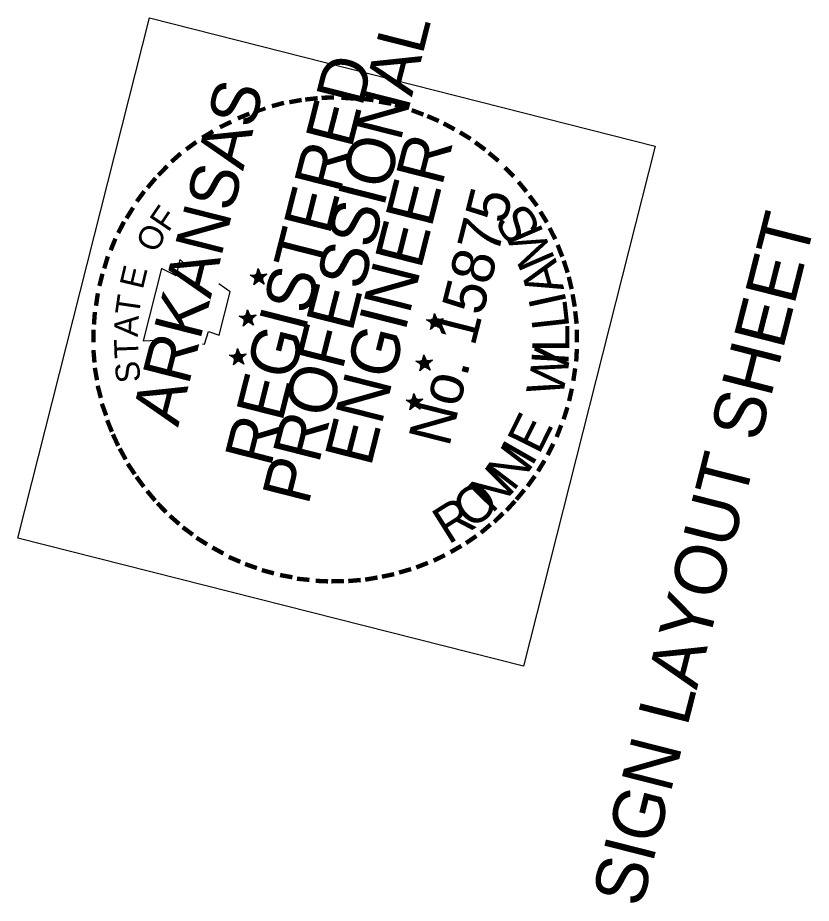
# Model space of a CAD drawing. Extents: x 670257 to 671518, y 737783 to 738188.
# Drawn here: x 670845.24 to 670853.49, y 738033.32 to 738042.53 of the extents above; entities that cross this region are included whole.
import ezdxf

# ---------------------------------------------------------------- set-up
doc = ezdxf.new("R2010")
doc.units = 0
for name, color, linetype in [('R_Border Notes', 7, 'Continuous'), ('R_Border PE', 7, 'Continuous'), ('R_Border Prem', 7, 'Continuous')]:
    doc.layers.add(name, color=color, linetype=linetype)

msp = doc.modelspace()

# ---------------------------------------------------------------- linework, layer by layer
at = {"layer": 'R_Border PE'}
for p, q in [((670847.7366, 738039.9206), (670847.7224, 738039.8443)), ((670847.7366, 738039.9206), (670847.7309, 738039.8473)), ((670847.7366, 738039.9206), (670847.7358, 738039.846)), ((670847.7366, 738039.9206), (670847.7418, 738039.829)), ((670847.7366, 738039.9206), (670847.7449, 738039.8618)), ((670847.7366, 738039.9206), (670847.748, 738039.8636)), ((670847.7366, 738039.9206), (670847.7516, 738039.8678)), ((670847.8274, 738039.8615), (670847.7418, 738039.829)), ((670847.8274, 738039.8615), (670847.7491, 738039.8478)), ((670847.8274, 738039.8615), (670847.7504, 738039.8527)), ((670847.8274, 738039.8615), (670847.7582, 738039.8429)), ((670847.8274, 738039.8615), (670847.7612, 738039.8241)), ((670847.8274, 738039.8615), (670847.766, 738039.8332)), ((670847.8274, 738039.8615), (670847.7684, 738039.8223)), ((670847.6545, 738039.8512), (670847.7194, 738039.8528)), ((670847.7418, 738039.829), (670847.6545, 738039.8512)), ((670847.6545, 738039.8512), (670847.7182, 738039.8479)), ((670847.6545, 738039.8512), (670847.7139, 738039.8413)), ((670847.6545, 738039.8512), (670847.7139, 738039.831)), ((670847.6545, 738039.8512), (670847.7127, 738039.8261)), ((670847.6545, 738039.8512), (670847.709, 738039.8219)), ((670847.6936, 738039.751), (670847.7418, 738039.829)), ((670847.6936, 738039.751), (670847.7169, 738039.8122)), ((670847.6936, 738039.751), (670847.7211, 738039.8085)), ((670847.6936, 738039.751), (670847.7235, 738039.8079)), ((670847.6936, 738039.751), (670847.7326, 738039.803)), ((670847.6936, 738039.751), (670847.7374, 738039.8018)), ((670847.6936, 738039.751), (670847.7423, 738039.8005)), ((670847.801, 738039.7573), (670847.7405, 738039.8036)), ((670847.801, 738039.7573), (670847.7418, 738039.829)), ((670847.801, 738039.7573), (670847.7484, 738039.8042)), ((670847.801, 738039.7573), (670847.752, 738039.8084)), ((670847.801, 738039.7573), (670847.7611, 738039.8138)), ((670847.801, 738039.7573), (670847.7612, 738039.8241)), ((670847.801, 738039.7573), (670847.7691, 738039.8247)), ((670847.6254, 738039.4923), (670847.6112, 738039.416)), ((670847.6254, 738039.4923), (670847.6197, 738039.419)), ((670847.6254, 738039.4923), (670847.6246, 738039.4177)), ((670847.6254, 738039.4923), (670847.6306, 738039.4007)), ((670847.6254, 738039.4923), (670847.6337, 738039.4335)), ((670847.6254, 738039.4923), (670847.6374, 738039.4377)), ((670847.6254, 738039.4923), (670847.6404, 738039.4395)), ((670847.5409, 738039.4235), (670847.6082, 738039.4245)), ((670847.6306, 738039.4007), (670847.5409, 738039.4235)), ((670847.5409, 738039.4235), (670847.6046, 738039.4202)), ((670847.5409, 738039.4235), (670847.6027, 738039.413)), ((670847.5409, 738039.4235), (670847.6003, 738039.4033)), ((670847.5409, 738039.4235), (670847.6015, 738039.3978)), ((670847.5409, 738039.4235), (670847.5984, 738039.396)), ((670847.5824, 738039.3227), (670847.6306, 738039.4007)), ((670847.7168, 738039.4356), (670847.6306, 738039.4007)), ((670847.6904, 738039.3314), (670847.6306, 738039.4007)), ((670847.7168, 738039.4356), (670847.6367, 738039.425)), ((670847.7168, 738039.4356), (670847.6379, 738039.4195)), ((670847.7168, 738039.4356), (670847.647, 738039.4146)), ((670847.7168, 738039.4356), (670847.65, 738039.3958)), ((670847.6904, 738039.3314), (670847.65, 738039.3958)), ((670847.7168, 738039.4356), (670847.6548, 738039.4049)), ((670847.7168, 738039.4356), (670847.6572, 738039.394)), ((670847.6904, 738039.3314), (670847.6578, 738039.3964)), ((670849.5704, 738039.4529), (670849.5569, 738039.379)), ((670849.5704, 738039.4529), (670849.5653, 738039.382)), ((670849.5704, 738039.4529), (670849.5702, 738039.3808)), ((670849.5704, 738039.4529), (670849.5762, 738039.3638)), ((670849.5704, 738039.4529), (670849.5787, 738039.3941)), ((670849.5704, 738039.4529), (670849.5848, 738039.3977)), ((670849.5704, 738039.4529), (670849.5878, 738039.3995)), ((670849.6618, 738039.3962), (670849.5762, 738039.3638)), ((670849.6618, 738039.3962), (670849.5829, 738039.3801)), ((670849.6618, 738039.3962), (670849.5842, 738039.385)), ((670849.6618, 738039.3962), (670849.5944, 738039.3746)), ((670849.6618, 738039.3962), (670849.5974, 738039.3558)), ((670849.6618, 738039.3962), (670849.5999, 738039.3655)), ((670849.6618, 738039.3962), (670849.6047, 738039.354)), ((670847.5824, 738039.3227), (670847.6032, 738039.3845)), ((670847.5824, 738039.3227), (670847.6081, 738039.3832)), ((670847.5824, 738039.3227), (670847.6123, 738039.3796)), ((670847.5824, 738039.3227), (670847.6214, 738039.3747)), ((670847.5824, 738039.3227), (670847.6262, 738039.3735)), ((670847.5824, 738039.3227), (670847.6311, 738039.3722)), ((670847.6904, 738039.3314), (670847.6293, 738039.3753)), ((670847.6904, 738039.3314), (670847.6372, 738039.3759)), ((670847.6904, 738039.3314), (670847.6408, 738039.3801)), ((670847.6904, 738039.3314), (670847.6499, 738039.3855)), ((670849.5762, 738039.3638), (670849.489, 738039.3859)), ((670849.489, 738039.3859), (670849.5532, 738039.3851)), ((670849.489, 738039.3859), (670849.5526, 738039.3827)), ((670849.489, 738039.3859), (670849.5508, 738039.3754)), ((670849.489, 738039.3859), (670849.5483, 738039.3657)), ((670849.489, 738039.3859), (670849.5471, 738039.3609)), ((670849.489, 738039.3859), (670849.5459, 738039.356)), ((670849.528, 738039.2857), (670849.5762, 738039.3638)), ((670849.528, 738039.2857), (670849.5507, 738039.3445)), ((670849.528, 738039.2857), (670849.5555, 738039.3433)), ((670849.528, 738039.2857), (670849.5597, 738039.3396)), ((670849.528, 738039.2857), (670849.567, 738039.3378)), ((670849.528, 738039.2857), (670849.5737, 738039.3335)), ((670849.528, 738039.2857), (670849.5785, 738039.3323)), ((670849.6354, 738039.292), (670849.5743, 738039.3359)), ((670849.6354, 738039.292), (670849.5762, 738039.3638)), ((670849.6354, 738039.292), (670849.5846, 738039.3359)), ((670849.6354, 738039.292), (670849.5889, 738039.3425)), ((670849.6354, 738039.292), (670849.5956, 738039.3486)), ((670849.6354, 738039.292), (670849.5974, 738039.3558)), ((670849.6354, 738039.292), (670849.6029, 738039.357)), ((670847.5228, 738039.0876), (670847.5086, 738039.0113)), ((670847.5228, 738039.0876), (670847.5171, 738039.0143)), ((670847.5228, 738039.0876), (670847.5219, 738039.0131)), ((670847.5228, 738039.0876), (670847.5279, 738038.9961)), ((670847.5228, 738039.0876), (670847.5311, 738039.0288)), ((670847.5228, 738039.0876), (670847.5347, 738039.033)), ((670847.5228, 738039.0876), (670847.5378, 738039.0348)), ((670847.6142, 738039.0309), (670847.5279, 738038.9961)), ((670847.6142, 738039.0309), (670847.5341, 738039.0203)), ((670847.6142, 738039.0309), (670847.5353, 738039.0148)), ((670847.6142, 738039.0309), (670847.5444, 738039.0099)), ((670847.6142, 738039.0309), (670847.5473, 738038.9911)), ((670847.6142, 738039.0309), (670847.5522, 738039.0002)), ((670847.6142, 738039.0309), (670847.5546, 738038.9893)), ((670849.4592, 738039.0246), (670849.4456, 738038.9507)), ((670849.4592, 738039.0246), (670849.4541, 738038.9537)), ((670849.4592, 738039.0246), (670849.459, 738038.9525)), ((670849.4592, 738039.0246), (670849.465, 738038.9355)), ((670849.4592, 738039.0246), (670849.4675, 738038.9658)), ((670849.4592, 738039.0246), (670849.4712, 738038.97)), ((670849.4592, 738039.0246), (670849.4773, 738038.9736)), ((670847.4383, 738039.0188), (670847.5056, 738039.0198)), ((670847.5279, 738038.9961), (670847.4383, 738039.0188)), ((670847.4383, 738039.0188), (670847.5019, 738039.0155)), ((670847.4383, 738039.0188), (670847.5007, 738039.0107)), ((670847.4383, 738039.0188), (670847.4982, 738039.001)), ((670847.4383, 738039.0188), (670847.4988, 738038.9931)), ((670847.4383, 738039.0188), (670847.4958, 738038.9913)), ((670847.4798, 738038.918), (670847.5279, 738038.9961)), ((670847.4798, 738038.918), (670847.5006, 738038.9798)), ((670847.4798, 738038.918), (670847.5054, 738038.9785)), ((670847.4798, 738038.918), (670847.5097, 738038.9749)), ((670847.4798, 738038.918), (670847.5194, 738038.9724)), ((670847.4798, 738038.918), (670847.5236, 738038.9688)), ((670847.4798, 738038.918), (670847.5284, 738038.9676)), ((670847.5877, 738038.9267), (670847.5266, 738038.9706)), ((670847.5877, 738038.9267), (670847.5279, 738038.9961)), ((670847.5877, 738038.9267), (670847.5345, 738038.9712)), ((670847.5877, 738038.9267), (670847.5382, 738038.9754)), ((670847.5877, 738038.9267), (670847.5473, 738038.9911)), ((670847.5877, 738038.9267), (670847.5473, 738038.9808)), ((670847.5877, 738038.9267), (670847.5552, 738038.9917)), ((670849.465, 738038.9355), (670849.3778, 738038.9576)), ((670849.3778, 738038.9576), (670849.442, 738038.9568)), ((670849.3778, 738038.9576), (670849.4414, 738038.9544)), ((670849.3778, 738038.9576), (670849.4396, 738038.9471)), ((670849.3778, 738038.9576), (670849.4371, 738038.9374)), ((670849.3778, 738038.9576), (670849.4359, 738038.9326)), ((670849.3778, 738038.9576), (670849.4322, 738038.9283)), ((670849.4168, 738038.8574), (670849.465, 738038.9355)), ((670849.5506, 738038.9679), (670849.465, 738038.9355)), ((670849.5242, 738038.8637), (670849.465, 738038.9355)), ((670849.5506, 738038.9679), (670849.4717, 738038.9518)), ((670849.5506, 738038.9679), (670849.4736, 738038.9591)), ((670849.5506, 738038.9679), (670849.4814, 738038.9494)), ((670849.5506, 738038.9679), (670849.4868, 738038.93)), ((670849.5506, 738038.9679), (670849.4886, 738038.9372)), ((670849.5506, 738038.9679), (670849.491, 738038.9263)), ((670849.4168, 738038.8574), (670849.4395, 738038.9162)), ((670849.4168, 738038.8574), (670849.4443, 738038.9149)), ((670849.4168, 738038.8574), (670849.4467, 738038.9143)), ((670849.4168, 738038.8574), (670849.4558, 738038.9094)), ((670849.4168, 738038.8574), (670849.4607, 738038.9082)), ((670849.4168, 738038.8574), (670849.4655, 738038.907)), ((670849.5242, 738038.8637), (670849.4637, 738038.91)), ((670849.5242, 738038.8637), (670849.474, 738038.91)), ((670849.5242, 738038.8637), (670849.4777, 738038.9142)), ((670849.5242, 738038.8637), (670849.4843, 738038.9203)), ((670849.5242, 738038.8637), (670849.4844, 738038.9306)), ((670849.5242, 738038.8637), (670849.4917, 738038.9287)), ((670849.3572, 738038.6224), (670849.343, 738038.546)), ((670849.3572, 738038.6224), (670849.3515, 738038.549)), ((670849.3572, 738038.6224), (670849.3564, 738038.5478)), ((670849.3572, 738038.6224), (670849.3624, 738038.5308)), ((670849.3572, 738038.6224), (670849.3649, 738038.5611)), ((670849.3572, 738038.6224), (670849.3685, 738038.5653)), ((670849.3572, 738038.6224), (670849.3746, 738038.569)), ((670849.2751, 738038.5529), (670849.34, 738038.5545)), ((670849.3624, 738038.5308), (670849.2751, 738038.5529)), ((670849.2751, 738038.5529), (670849.3388, 738038.5497)), ((670849.2751, 738038.5529), (670849.3369, 738038.5424)), ((670849.2751, 738038.5529), (670849.3345, 738038.5327)), ((670849.2751, 738038.5529), (670849.3332, 738038.5279)), ((670849.2751, 738038.5529), (670849.3296, 738038.5236)), ((670849.3142, 738038.4527), (670849.3624, 738038.5308)), ((670849.3142, 738038.4527), (670849.3374, 738038.5139)), ((670849.3142, 738038.4527), (670849.3417, 738038.5103)), ((670849.3142, 738038.4527), (670849.3441, 738038.5096)), ((670849.3142, 738038.4527), (670849.3532, 738038.5048)), ((670849.3142, 738038.4527), (670849.358, 738038.5035)), ((670849.3142, 738038.4527), (670849.3629, 738038.5023)), ((670849.4215, 738038.4591), (670849.3611, 738038.5053)), ((670849.448, 738038.5633), (670849.3624, 738038.5308)), ((670849.4215, 738038.4591), (670849.3624, 738038.5308)), ((670849.448, 738038.5633), (670849.3691, 738038.5472)), ((670849.448, 738038.5633), (670849.3709, 738038.5544)), ((670849.4215, 738038.4591), (670849.3714, 738038.5053)), ((670849.4215, 738038.4591), (670849.375, 738038.5095)), ((670849.448, 738038.5633), (670849.3788, 738038.5447)), ((670849.4215, 738038.4591), (670849.3817, 738038.5259)), ((670849.4215, 738038.4591), (670849.3817, 738038.5156)), ((670849.448, 738038.5633), (670849.3842, 738038.5253)), ((670849.448, 738038.5633), (670849.386, 738038.5325)), ((670849.448, 738038.5633), (670849.3884, 738038.5216)), ((670849.4215, 738038.4591), (670849.389, 738038.524))]:
    msp.add_line(p, q, dxfattribs=at)
for points in [[(670846.9813, 738039.9626), (670846.922, 738040.0137), (670846.8845, 738039.8453), (670846.7338, 738039.9222), (670846.5426, 738039.1686)], [(670847.6545, 738039.8512), (670847.8274, 738039.8615), (670847.6936, 738039.751), (670847.7366, 738039.9206), (670847.801, 738039.7573), (670847.6545, 738039.8512)], [(670847.1592, 738039.1386), (670847.181, 738039.1331), (670847.2202, 738039.2675), (670847.3311, 738039.2265), (670847.446, 738039.6797), (670847.3298, 738039.7607)], [(670847.5409, 738039.4235), (670847.7168, 738039.4356), (670847.5824, 738039.3227), (670847.6254, 738039.4923), (670847.6904, 738039.3314), (670847.5409, 738039.4235)], [(670849.489, 738039.3859), (670849.6618, 738039.3962), (670849.528, 738039.2857), (670849.5704, 738039.4529), (670849.6354, 738039.292), (670849.489, 738039.3859)], [(670846.5426, 738039.1686), (670846.7597, 738039.1806)], [(670847.4383, 738039.0188), (670847.6142, 738039.0309), (670847.4798, 738038.918), (670847.5228, 738039.0876), (670847.5877, 738038.9267), (670847.4383, 738039.0188)], [(670849.3778, 738038.9576), (670849.5506, 738038.9679), (670849.4168, 738038.8574), (670849.4592, 738039.0246), (670849.5242, 738038.8637), (670849.3778, 738038.9576)], [(670849.2751, 738038.5529), (670849.448, 738038.5633), (670849.3142, 738038.4527), (670849.3572, 738038.6224), (670849.4215, 738038.4591), (670849.2751, 738038.5529)]]:
    msp.add_lwpolyline(points, dxfattribs=at)
for centre, radius in [((670847.7423, 738039.8287), 0.0431), ((670847.7423, 738039.8287), 0.039), ((670847.7423, 738039.8287), 0.0361), ((670847.7423, 738039.8287), 0.0332), ((670847.7423, 738039.8287), 0.0289), ((670847.7423, 738039.8287), 0.0269), ((670847.7423, 738039.8287), 0.0248), ((670847.7423, 738039.8287), 0.0213), ((670847.7423, 738039.8287), 0.0187), ((670847.7423, 738039.8287), 0.0155), ((670847.7423, 738039.8287), 0.0124), ((670847.7423, 738039.8287), 0.00924), ((670847.7423, 738039.8287), 0.00741), ((670847.7423, 738039.8287), 0.0036), ((670847.6309, 738039.4012), 0.0431), ((670847.6309, 738039.4012), 0.039), ((670847.6309, 738039.4012), 0.0361), ((670847.6309, 738039.4012), 0.0332), ((670847.6309, 738039.4012), 0.0289), ((670847.6309, 738039.4012), 0.0269), ((670847.6309, 738039.4012), 0.0248), ((670847.6309, 738039.4012), 0.0213), ((670847.6309, 738039.4012), 0.0187), ((670847.6309, 738039.4012), 0.0155), ((670847.6309, 738039.4012), 0.0124), ((670847.6309, 738039.4012), 0.00924), ((670847.6309, 738039.4012), 0.00741), ((670847.6309, 738039.4012), 0.0036), ((670849.5773, 738039.3623), 0.0431), ((670849.5773, 738039.3623), 0.039), ((670849.5773, 738039.3623), 0.0361), ((670849.5773, 738039.3623), 0.0332), ((670849.5773, 738039.3623), 0.0289), ((670849.5773, 738039.3623), 0.0269), ((670849.5773, 738039.3623), 0.0248), ((670849.5773, 738039.3623), 0.0213), ((670849.5773, 738039.3623), 0.0187), ((670849.5773, 738039.3623), 0.0155), ((670849.5773, 738039.3623), 0.0124), ((670849.5773, 738039.3623), 0.00924), ((670849.5773, 738039.3623), 0.00741), ((670849.5773, 738039.3623), 0.0036), ((670847.5283, 738038.9967), 0.0431), ((670847.5283, 738038.9967), 0.039), ((670847.5283, 738038.9967), 0.0361), ((670847.5283, 738038.9967), 0.0332), ((670847.5283, 738038.9967), 0.0289), ((670847.5283, 738038.9967), 0.0269), ((670847.5283, 738038.9967), 0.0248), ((670847.5283, 738038.9967), 0.0213), ((670847.5283, 738038.9967), 0.0187), ((670847.5283, 738038.9967), 0.0155), ((670847.5283, 738038.9967), 0.0124), ((670847.5283, 738038.9967), 0.00924), ((670847.5283, 738038.9967), 0.00741), ((670847.5283, 738038.9967), 0.0036), ((670849.4658, 738038.9348), 0.0431), ((670849.4658, 738038.9348), 0.039), ((670849.4658, 738038.9348), 0.0361), ((670849.4658, 738038.9348), 0.0332), ((670849.4658, 738038.9348), 0.0289), ((670849.4658, 738038.9348), 0.0269), ((670849.4658, 738038.9348), 0.0248), ((670849.4658, 738038.9348), 0.0213), ((670849.4658, 738038.9348), 0.0187), ((670849.4658, 738038.9348), 0.0155), ((670849.4658, 738038.9348), 0.0124), ((670849.4658, 738038.9348), 0.00924), ((670849.4658, 738038.9348), 0.00741), ((670849.4658, 738038.9348), 0.0036), ((670849.3632, 738038.5303), 0.0431), ((670849.3632, 738038.5303), 0.039), ((670849.3632, 738038.5303), 0.0361), ((670849.3632, 738038.5303), 0.0332), ((670849.3632, 738038.5303), 0.0289), ((670849.3632, 738038.5303), 0.0269), ((670849.3632, 738038.5303), 0.0248), ((670849.3632, 738038.5303), 0.0213), ((670849.3632, 738038.5303), 0.0187), ((670849.3632, 738038.5303), 0.0155), ((670849.3632, 738038.5303), 0.0124), ((670849.3632, 738038.5303), 0.00924), ((670849.3632, 738038.5303), 0.00741), ((670849.3632, 738038.5303), 0.0036)]:
    msp.add_circle(centre, radius, dxfattribs=at)
at = {"layer": 'R_Border Prem'}
msp.add_lwpolyline([(670845.2368, 738037.1189), (670846.6086, 738042.5277), (670851.867, 738041.194), (670850.4952, 738035.7853)], close=True, dxfattribs=at)

# ---------------------------------------------------------------- texts
at = {"layer": 'R_Border Notes'}
msp.add_text('SIGN LAYOUT SHEET', height=0.533593, rotation=75.76855, dxfattribs=at).set_placement((670851.7216, 738033.2648))
at = {"layer": 'R_Border PE'}
for s, height, rotation, p in [('PROFESSIONAL', 0.499995, 75.76855, (670848.2576, 738037.4492)), ('REGISTERED', 0.5, 75.76855, (670847.8678, 738037.8447)), ('ARKANSAS', 0.5, 75.76855, (670846.9039, 738038.2645)), ('-', 0.3999, 10.43135, (670848.0658, 738041.493)), ('-', 0.3999, 6.34138, (670848.2199, 738041.5209)), ('-', 0.4, 0.89181, (670848.3746, 738041.541)), ('-', 0.4, 356.31789, (670848.5686, 738041.5434)), ('-', 0.4, 352.36471, (670848.7632, 738041.5379)), ('-', 0.35, 19.44384, (670847.7308, 738041.4129)), ('-', 0.4, 15.4369, (670847.8983, 738041.4529)), ('-', 0.4, 350.09866, (670848.9438, 738041.5076)), ('-', 0.3999, 345.70922, (670849.0983, 738041.4761)), ('-', 0.3999, 22.42073, (670847.5626, 738041.3291)), ('-', 0.3999, 339.28575, (670849.257, 738041.4307)), ('-', 0.4, 336.76384, (670849.4127, 738041.3732)), ('-', 0.3999, 25.64828, (670847.3852, 738041.24)), ('-', 0.3999, 331.53115, (670849.5707, 738041.3047)), ('-', 0.4, 31.34714, (670847.2169, 738041.1357)), ('-', 0.4, 328.63664, (670849.7341, 738041.2168)), ('-', 0.4, 36.29826, (670847.0613, 738041.0204)), ('ENGINEER', 0.5, 75.76855, (670848.9083, 738037.849)), ('-', 0.4, 323.65722, (670849.8829, 738041.1224)), ('-', 0.3999, 41.63121, (670846.9196, 738040.899)), ('-', 0.4, 320.38827, (670850.019, 738041.0182)), ('-', 0.3999, 45.40945, (670846.793, 738040.766)), ('-', 0.4, 314.8398, (670850.1768, 738040.8776)), ('-', 0.4, 49.88964, (670846.6895, 738040.6427)), ('-', 0.4, 309.61379, (670850.3097, 738040.7407)), ('-', 0.4, 53.62364, (670846.5854, 738040.5066)), ('No. 15875', 0.44, 75.76855, (670849.7214, 738038.055)), ('-', 0.4, 307.02232, (670850.4214, 738040.6015)), ('-', 0.4, 58.10475, (670846.4866, 738040.3408)), ('F', 0.2499, 55.83921, (670846.8011, 738040.2894)), ('S', 0.3849, 121.46196, (670850.6904, 738040.3299)), ('-', 0.3999, 301.53388, (670850.5276, 738040.4508)), ('-', 0.4, 62.97344, (670846.4091, 738040.198)), ('O', 0.2499, 66.22005, (670846.687, 738040.0734)), ('M', 0.3849, 113.32556, (670850.8313, 738040.0141)), ('-', 0.3999, 296.85364, (670850.6192, 738040.2934)), ('-', 0.4, 67.93028, (670846.3382, 738040.0303)), ('-', 0.3999, 291.50488, (670850.6993, 738040.1312)), ('-', 0.4, 73.51159, (670846.2782, 738039.8546)), ('E', 0.25, 76.60089, (670846.5371, 738039.6961)), ('A', 0.3849, 105.76014, (670850.921, 738039.7052)), ('-', 0.4, 288.01764, (670850.7607, 738039.9764)), ('-', 0.3999, 75.95478, (670846.2309, 738039.6784)), ('-', 0.4, 283.12539, (670850.8117, 738039.8216)), ('-', 0.3999, 81.66537, (670846.2005, 738039.4875)), ('T', 0.25, 81.79131, (670846.4962, 738039.4228)), ('I', 0.3849, 102.33428, (670850.9481, 738039.562)), ('-', 0.3999, 280.02017, (670850.8505, 738039.6493)), ('L', 0.3849, 96.33904, (670850.9747, 738039.3085)), ('-', 0.4, 85.9879, (670846.1823, 738039.3038)), ('A', 0.25, 86.98173, (670846.4851, 738039.2064)), ('-', 0.4, 276.48697, (670850.8778, 738039.4824)), ('L', 0.3849, 90.3438, (670850.9746, 738039.0535)), ('-', 0.3999, 89.3987, (670846.1793, 738039.1292)), ('-', 0.3999, 271.24284, (670850.8948, 738039.3053)), ('T', 0.2499, 92.17215, (670846.4947, 738038.9899)), ('W', 0.3849, 78.78155, (670850.8996, 738038.5683)), ('-', 0.3999, 94.94463, (670846.1913, 738038.9327)), ('I', 0.3849, 86.91795, (670850.9626, 738038.9083)), ('-', 0.4, 267.05431, (670850.8984, 738039.1161)), ('S', 0.2499, 97.36257, (670846.5187, 738038.7491)), ('-', 0.4, 100.07576, (670846.218, 738038.7634)), ('-', 0.3999, 261.58522, (670850.8844, 738038.9288)), ('-', 0.4, 104.56037, (670846.2569, 738038.5911)), ('-', 0.4, 257.36031, (670850.854, 738038.7276)), ('-', 0.4, 109.83212, (670846.3097, 738038.423)), ('-', 0.4, 252.28682, (670850.8134, 738038.5471)), ('E', 0.3849, 63.72208, (670850.6593, 738037.9764)), ('-', 0.3999, 112.00029, (670846.3685, 738038.2584)), ('-', 0.4, 248.88401, (670850.7528, 738038.369)), ('-', 0.3999, 114.71921, (670846.4317, 738038.1212)), ('I', 0.3849, 60.29623, (670850.5835, 738037.8519)), ('-', 0.4, 243.32407, (670850.6788, 738038.1892)), ('-', 0.3999, 118.7308, (670846.5065, 738037.9888)), ('N', 0.3849, 52.7308, (670850.3907, 738037.5945)), ('-', 0.4, 238.56682, (670850.5958, 738038.0246)), ('-', 0.4, 124.1916, (670846.5951, 738037.8502)), ('N', 0.3849, 45.16538, (670850.1656, 738037.3648)), ('-', 0.3999, 126.38273, (670846.6868, 738037.7238)), ('-', 0.4, 234.32977, (670850.5031, 738037.8727)), ('O', 0.3849, 38.88465, (670849.9571, 738037.1979)), ('-', 0.4, 130.00102, (670846.7998, 738037.5894)), ('-', 0.3999, 230.36875, (670850.4013, 738037.736)), ('-', 0.4, 133.83918, (670846.9079, 738037.4769)), ('R', 0.3849, 32.17569, (670849.7157, 738037.046)), ('-', 0.3999, 227.33894, (670850.3112, 738037.6247)), ('-', 0.3999, 138.6399, (670847.0367, 738037.3642)), ('-', 0.4, 223.85834, (670850.1956, 738037.5045)), ('-', 0.3999, 220.41489, (670850.0715, 738037.3915)), ('-', 0.3999, 143.54282, (670847.1685, 738037.2637)), ('-', 0.3999, 148.16302, (670847.3077, 738037.1717)), ('-', 0.4, 214.70237, (670849.9378, 738037.281)), ('-', 0.4, 151.22951, (670847.4705, 738037.0814)), ('-', 0.4, 209.99236, (670849.7943, 738037.1833)), ('-', 0.3999, 156.96982, (670847.6339, 738037.0039)), ('-', 0.3999, 206.48667, (670849.6315, 738037.0904)), ('-', 0.3999, 160.95489, (670847.7968, 738036.9445)), ('-', 0.4, 196.21567, (670849.3073, 738036.9509)), ('-', 0.4, 201.662, (670849.4675, 738037.0134)), ('-', 0.4, 164.83079, (670847.9646, 738036.8942)), ('-', 0.3999, 169.96443, (670848.144, 738036.859)), ('-', 0.3999, 189.83287, (670848.9759, 738036.8647)), ('-', 0.3999, 191.4974, (670849.1446, 738036.8993)), ('-', 0.3999, 174.71648, (670848.3082, 738036.8354)), ('-', 0.4, 177.4835, (670848.4955, 738036.8214)), ('-', 0.4, 181.2264, (670848.6489, 738036.8264)), ('-', 0.3999, 184.85597, (670848.8145, 738036.8385))]:
    msp.add_text(s, height=height, rotation=rotation, dxfattribs=at).set_placement(p)

doc.saveas('drawing.dxf')
